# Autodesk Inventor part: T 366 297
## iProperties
Created: 2005-12
Part Number: T 366 297
Material: 1.0161
Description: Vierkantrohr
Vendor: Autodesk Inc.
Document SubType Name: Modeling
Standard: ISO 4019
Designer: I.Baliuc
Size Designation: 34x34x3 - 80
Density: 7.84 g/cm^3
Zweck: für DC - Schalter
Abmessung: Vkt Rohr 34x3-80
G_L: 80,000 mm
Author: T.Messerschmitt
Revision Number: 366297
Keywords: 381025
Comments: ISO 4019 - 1982 (rechteckig) 34x34x3 - 80
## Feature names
1. Körper [Extrusion]
2. Rundung1 [Fillet]
3. Rundung2 [Fillet]
4. Bohrung1 [Hole]
5. Bohrung2 [Hole]
6. Bohrung3 [Hole]
